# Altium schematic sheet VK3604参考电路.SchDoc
size A4
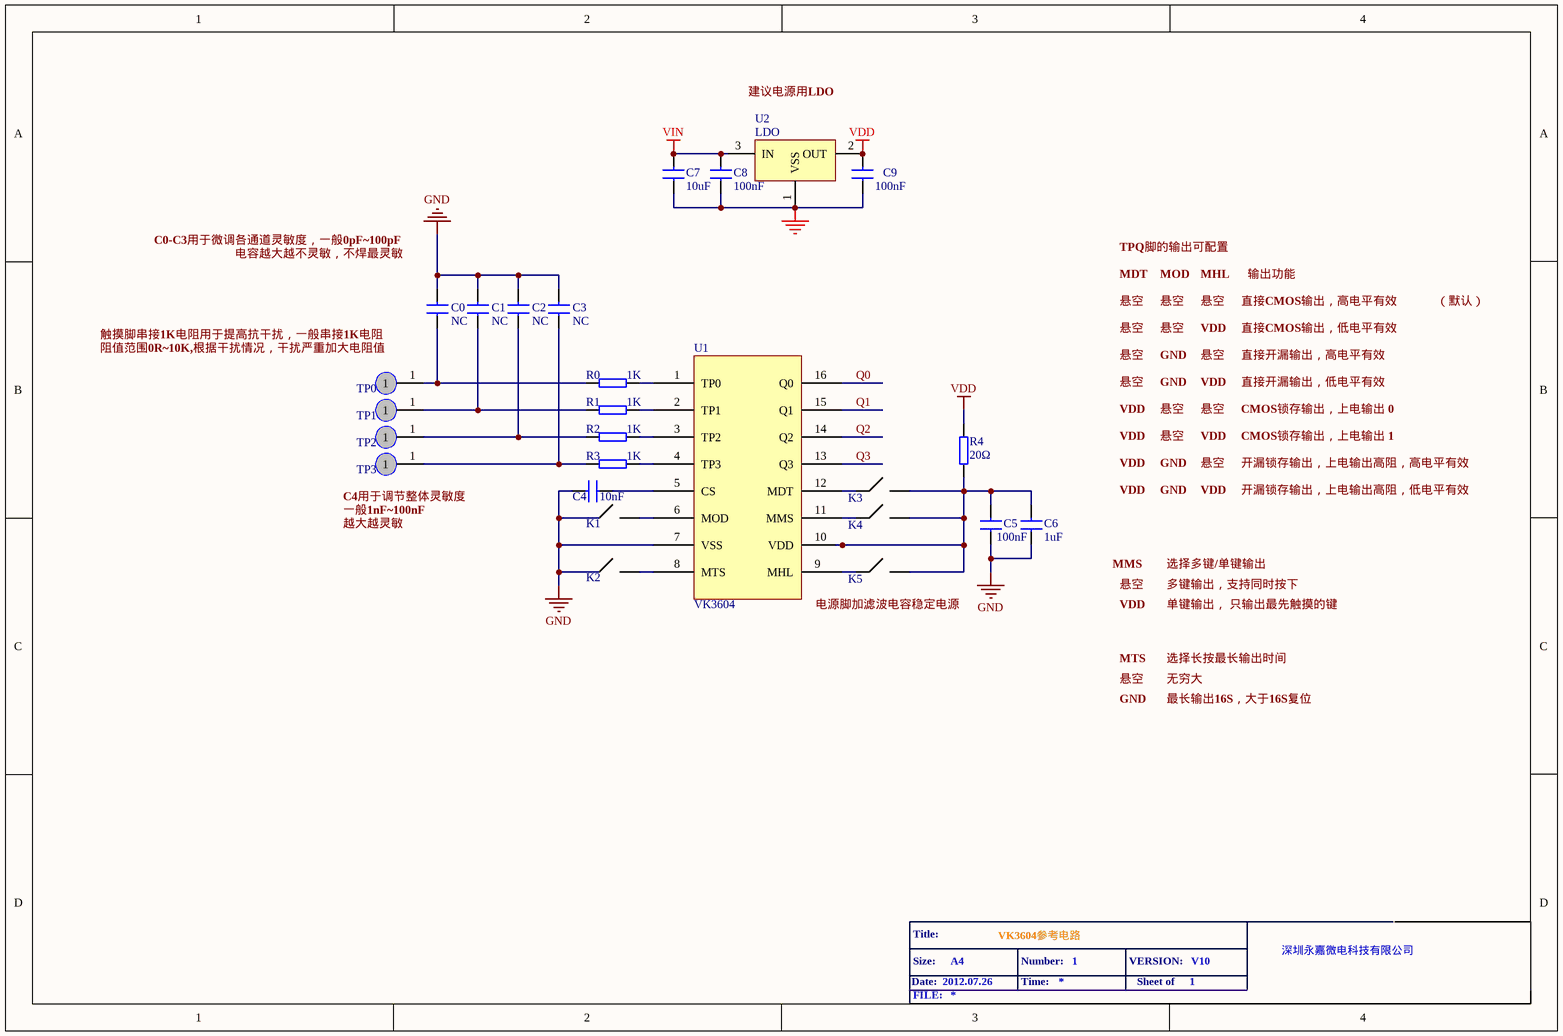
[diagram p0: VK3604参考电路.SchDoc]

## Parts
C0  value NC  [0603-C]  (hidden comment: 10uF)
C1  value NC  [0603-C]  (hidden comment: 10uF)
C2  value NC  [0603-C]  (hidden comment: 10uF)
C3  value NC  [0603-C]  (hidden comment: 10uF)
C4  value 10nF  [0603-C]  (hidden comment: 10uF)
C5  100nF  [0603-C]
C6  value 1uF  [0603-C]  (hidden comment: 10uF)
C7  10uF  [0805-C]
C8  100nF  [0805-C]
C9  100nF  [0805-C]
K1  单刀单掷开关  (value not drawn)
K2  单刀单掷开关  (value not drawn)
K3  单刀单掷开关  (value not drawn)
K4  单刀单掷开关  (value not drawn)
K5  单刀单掷开关  (value not drawn)
R0  1K  [0603-R]
R1  1K  [0603-R]
R2  1K  [0603-R]
R3  1K  [0603-R]
R4  20Ω  [0603-R]
TP0  TPAD  [TP-PAD0]  (value not drawn)
TP1  TPAD  [TP-PAD0]  (value not drawn)
TP2  TPAD  [TP-PAD0]  (value not drawn)
TP3  TPAD  [TP-PAD0]  (value not drawn)
U1  VK3604
U2  LDO  [SOT-23]

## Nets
GND: C0.2 C1.2 C2.2 C3.2 C4.2 C5.2 C6.2 C7.2 C8.2 C9.2 U1.7(VSS) U2.1(VSS)
VDD: C9.1 R4.2 U2.2(OUT)
VIN: C7.1 C8.1 U2.3(IN)
Q0: U1.16(Q0)
Q1: U1.15(Q1)
Q2: U1.14(Q2)
Q3: U1.13(Q3)
NetC0_1: C0.1 R0.2 TP0.1
NetC1_1: C1.1 R1.2 TP1.1
NetC2_1: C2.1 R2.2 TP2.1
NetC3_1: C3.1 R3.2 TP3.1
NetC4_1: C4.1 U1.5(CS)
NetC5_1: C5.1 C6.1 R4.1 U1.10(VDD)
NetR0_1: R0.1 U1.1(TP0)
NetR1_1: R1.1 U1.2(TP1)
NetR2_1: R2.1 U1.3(TP2)
NetR3_1: R3.1 U1.4(TP3)

Not connected (* = marked no-connect by the designer): U1 6(MOD) 8(MTS) 9(MHL) 11(MMS) 12(MDT)

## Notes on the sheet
- 建议电源用LDO
- C0-C3用于微调各通道灵敏度，一般0pF
  00pF
- TPQ脚的输出可配置
- 电容越大越不灵敏，不焊最灵敏
- MDT
- 悬空
- MOD
- MHL
- 直接CMOS输出，高电平有效
- 输出功能
- （默认）
- 触摸脚串接1K电阻用于提高抗干扰，一般串接1K电阻
- 阻值范围0R
  0K,根据干扰情况，干扰严重加大电阻值
- GND
- VDD
- 直接CMOS输出，低电平有效
- 直接开漏输出，高电平有效
- 直接开漏输出，低电平有效
- CMOS锁存输出，上电输出 0
- CMOS锁存输出，上电输出 1
- (near TP3) C4用于调节整体灵敏度
- (near TP3) 一般1nF
  00nF
- 开漏锁存输出，上电输出高阻，高电平有效
- 开漏锁存输出，上电输出高阻，低电平有效
- 越大越灵敏
- MMS
- 选择多键/单键输出
- 电源脚加滤波电容稳定电源
- 多键输出，支持同时按下
- 单键输出， 只输出最先触摸的键
- MTS
- 选择长按最长输出时间
- 无穷大
- 最长输出16S，大于16S复位
- Date:
- Title:
- Size:
- 2012.07.26
- A4
- VK3604参考电路
- Number:
- Time:
- 1
- VERSION:
- Sheet of
- V10
- 深圳永嘉微电科技有限公司
- FILE:

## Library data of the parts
C0-C9 = CAP: Capacitor
R0-R4 = RES: Resistor
TP0-TP3 = TPAD: TESTING
U2 = V6206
